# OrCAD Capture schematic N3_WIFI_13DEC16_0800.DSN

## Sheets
1 PAGE2: size C
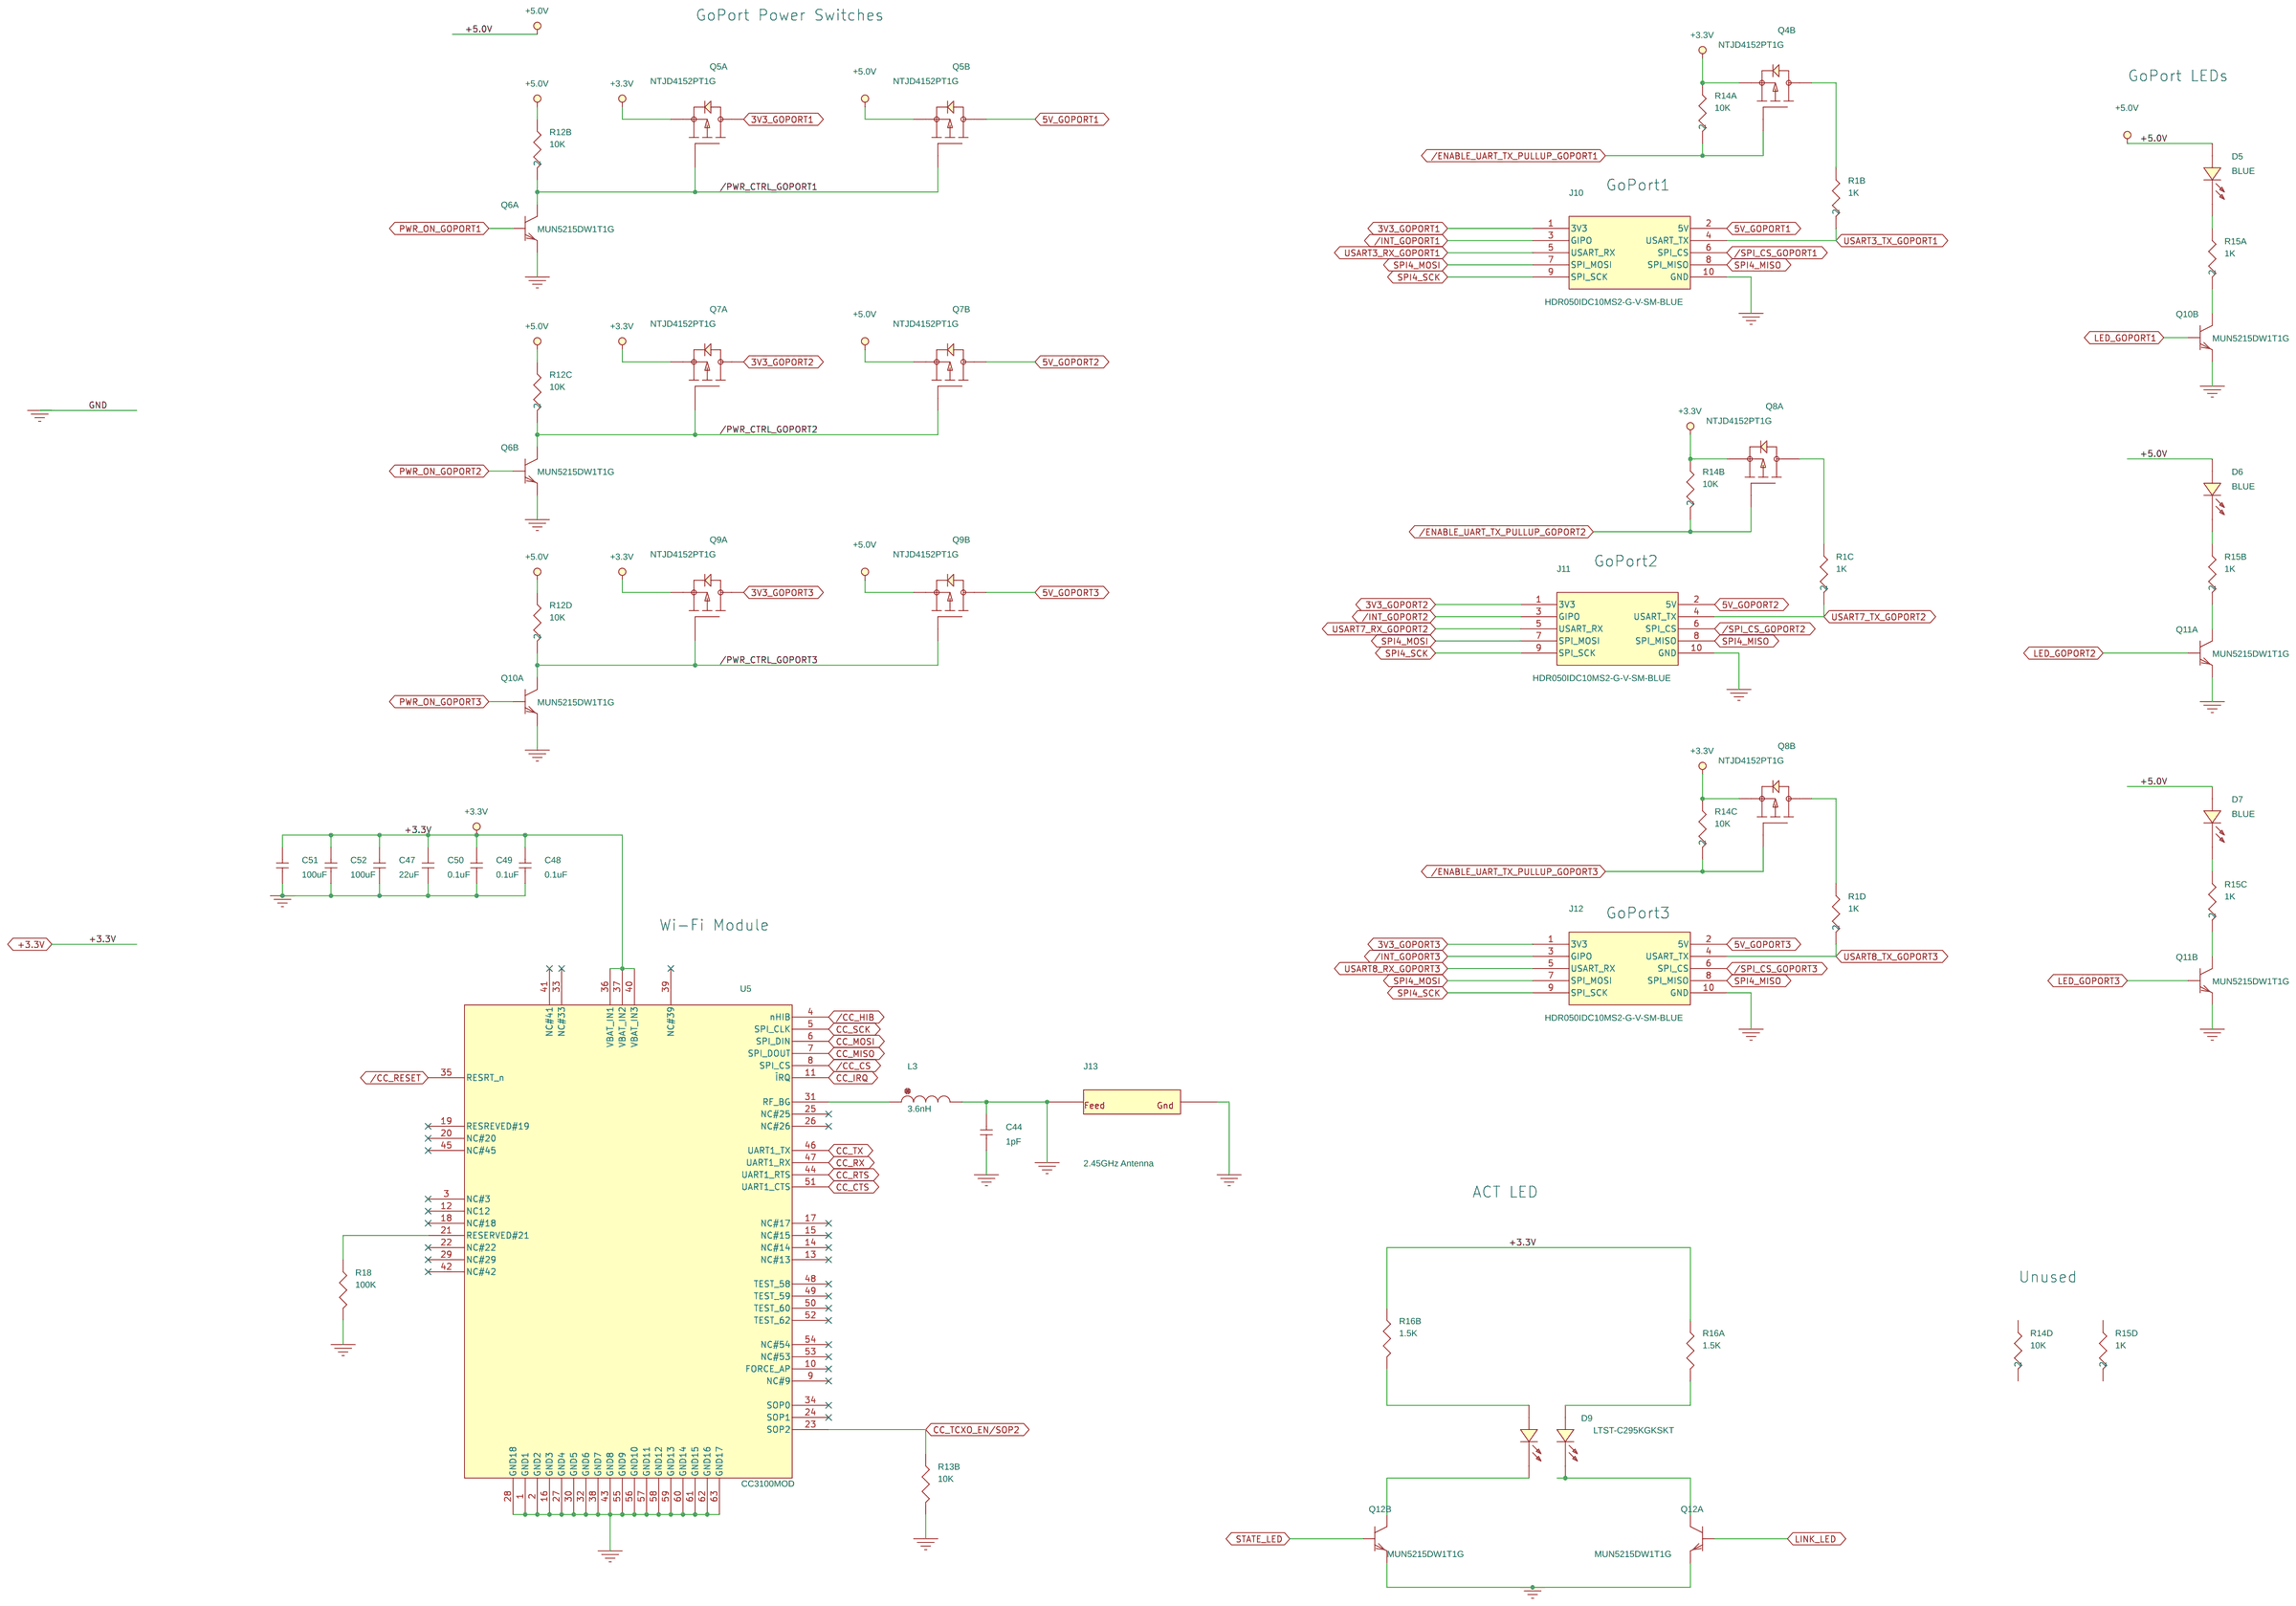
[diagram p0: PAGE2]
2 PAGE1: size C
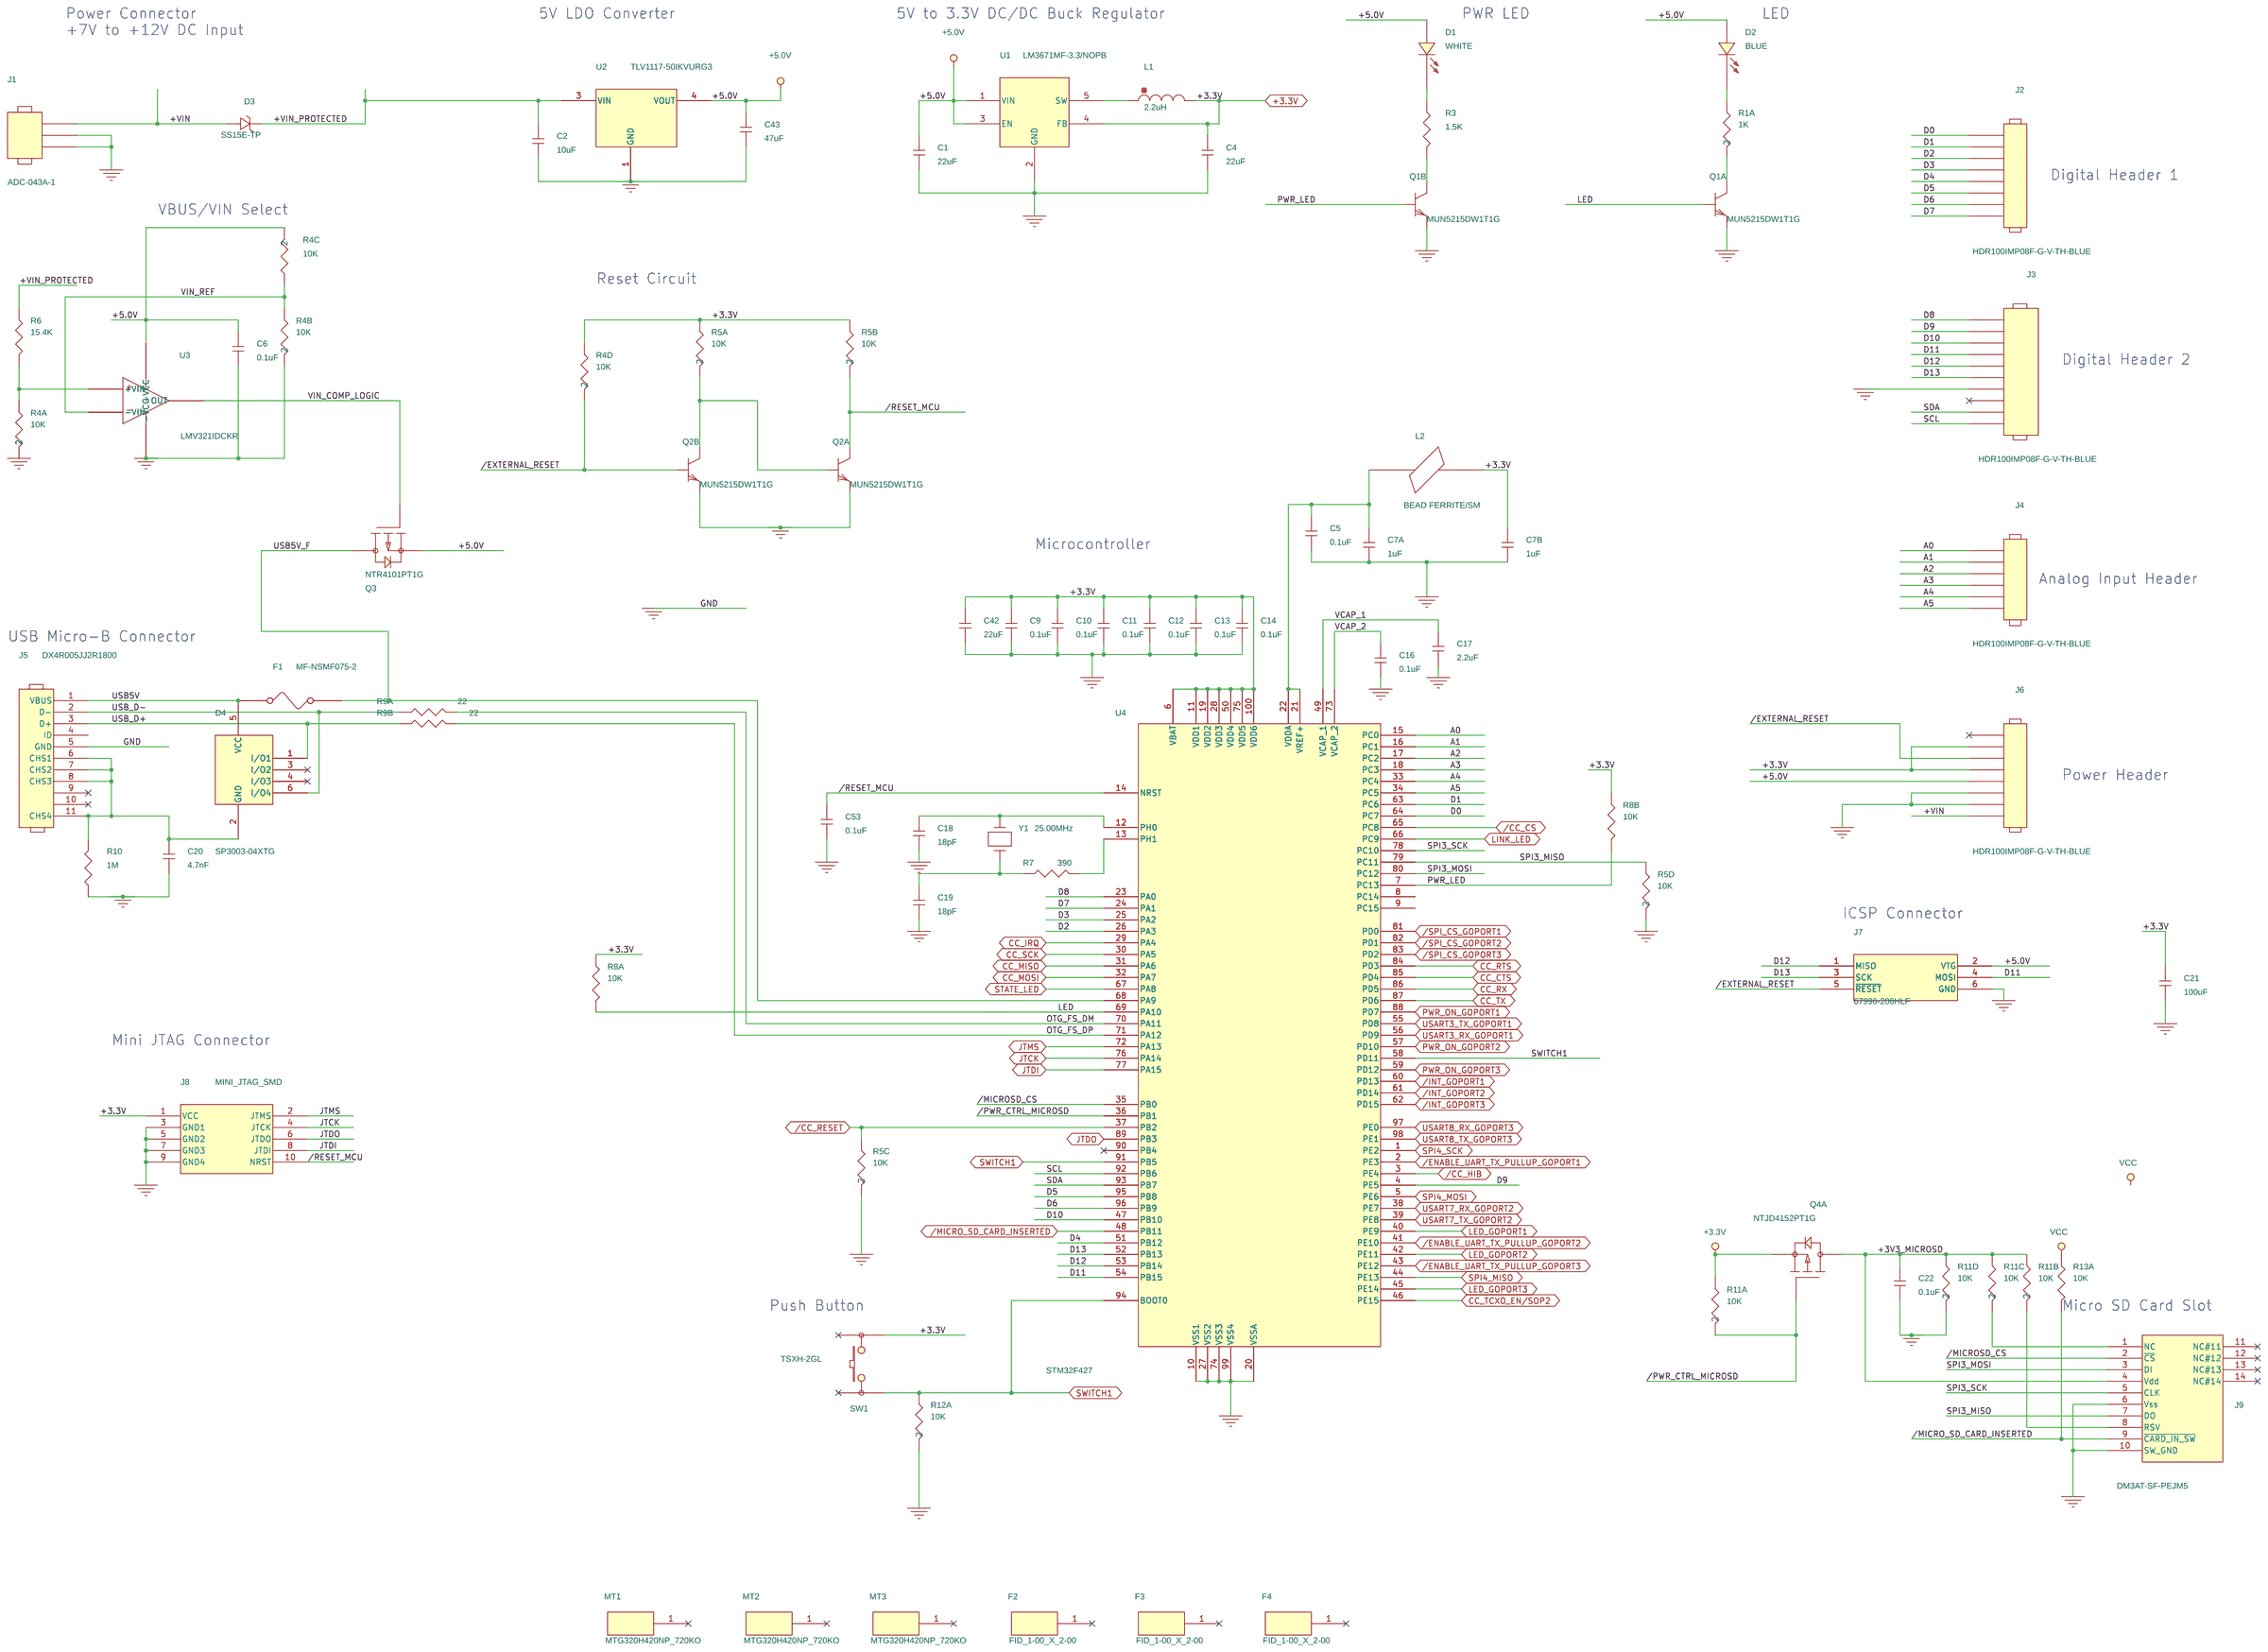
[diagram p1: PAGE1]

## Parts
sheet PAGE1
C1  22uF  [CAPC3216X180N]
C2  10uF  [CAPC2012X125N]
C4  22uF  [CAPC2012X125N]
C5  0.1uF  [CAPC1005X55N]
C6  0.1uF  [CAPC1005X55N]
C7  1uF  [GNM1M2]  (sections A,B)
C9  0.1uF  [CAP-0201]
C10  0.1uF  [CAPC1005X55N]
C11  0.1uF  [CAPC1005X55N]
C12  0.1uF  [CAPC1005X55N]
C13  0.1uF  [CAPC1005X55N]
C14  0.1uF  [CAPC1005X55N]
C16  0.1uF  [CAPC1005X55N]
C17  2.2uF  [CAPC1005X55N]
C18  18pF  [CAPC1005X55N]
C19  18pF  [CAPC1005X55N]
C20  4.7nF  [CAPC1005X55N]
C21  100uF  [CAPMP6032X280N]
C22  0.1uF  [CAPC1005X55N]
C42  22uF  [CAPC2012X125N]
C43  47uF  [F931A476MBA]
C53  0.1uF  [CAP-0201]
D1  WHITE  [LEDC2012X110N]
D2  BLUE  [LEDC2012X110N]
D3  SS15E-TP  [SS15-TP]
D4  SP3003-04XTG  [SP3003-04XTG]
F1  MF-NSMF075-2  [RESC3216X100N]
F2  FID_1-00_X_2-00  [FID_1-00_X_2-00]
F3  FID_1-00_X_2-00  [FID_1-00_X_2-00]
F4  FID_1-00_X_2-00  [FID_1-00_X_2-00]
J1  ADC-043A-1  [ADC-043A-1]
J2  HDR100IMP08F-G-V-TH-BLUE  [HDR100IMP08F-G-V-TH]
J3  HDR100IMP08F-G-V-TH-BLUE  [HDR100IMP10F-G-V-TH]
J4  HDR100IMP08F-G-V-TH-BLUE  [HDR100IMP06F-G-V-TH]
J5  DX4R005JJ2R1800  [DX4R005JJ2R1800]
J6  HDR100IMP08F-G-V-TH-BLUE  [HDR100IMP08F-G-V-TH]
J7  67996-206HLF  [67996-206HLF]
J8  MINI_JTAG_SMD  [MINI_JTAG_SMD]
J9  DM3AT-SF-PEJM5  [DM3AT-SF-PEJ]
L1  2.2uH  [LQH3NPN2R2NM0L]
L2  BEAD FERRITE/SM  [INDC1005X55N]
MT1  MTG320H420NP_720KO  [MTG320H420NP_720KO]
MT2  MTG320H420NP_720KO  [MTG320H420NP_720KO]
MT3  MTG320H420NP_720KO  [MTG320H420NP_720KO]
Q1  MUN5215DW1T1G  [MUN5215DW1T1G]  (sections A,B)
Q2  MUN5215DW1T1G  [MUN5215DW1T1G]  (sections A,B)
Q3  NTR4101PT1G  [NTR4101PT1G]
R3  1.5K  [RESC1005X40AN]
R4  10K  [RESCAV50P80X160X60-8N]  (sections A,B,C,D)
R5  10K  [RESCAV50P80X160X60-8N]  (sections A,B,C,D)
R6  15.4K  [RESC1005X40AN]
R7  390  [RESC1005X40AN]
R8  10K  [EXB24V]  (sections A,B)
R9  22  [EXB24V]  (sections A,B)
R10  1M  [RESC1005X40AN]
R11  10K  [RESCAV50P80X160X60-8N]  (sections A,B,C,D)
SW1  TSXH-2GL  [TSXH-2GL]
U1  LM3671MF-3.3/NOPB  [LM3671MF]
U2  TLV1117-50IKVURG3  [TLV1117-50IKVURG3]
U3  LMV321IDCKR  [LMV321IDCKR]
U4  STM32F427  [STM32F427VIT6]
Y1  25.00MHz  [ABM7]
sheet PAGE2
C44  1pF  [CAPC1005X55N]
C47  22uF  [CAPC2012X125N]
C48  0.1uF  [CAPC1005X55N]
C49  0.1uF  [CAPC1005X55N]
C50  0.1uF  [CAPC1005X55N]
C51  100uF  [CAPMP6032X280N]
C52  100uF  [CAPMP6032X280N]
D5  BLUE  [LEDC1608X80N]
D6  BLUE  [LEDC1608X80N]
D7  BLUE  [LEDC1608X80N]
D9  LTST-C295KGKSKT  [LTST-C295]
J10  HDR050IDC10MS2-G-V-SM-BLUE  [20021521-00010T1LF]
J11  HDR050IDC10MS2-G-V-SM-BLUE  [20021521-00010T1LF]
J12  HDR050IDC10MS2-G-V-SM-BLUE  [20021521-00010T1LF]
J13  2.45GHz Antenna  [AH316M245001-T]
L3  3.6nH  [RESC1005X40AN]
Q4  NTJD4152PT1G  [NTJD4152PT1G]  (sections A,B)
Q5  NTJD4152PT1G  [NTJD4152PT1G]  (sections A,B)
Q6  MUN5215DW1T1G  [MUN5215DW1T1G]  (sections A,B)
Q7  NTJD4152PT1G  [NTJD4152PT1G]  (sections A,B)
Q8  NTJD4152PT1G  [NTJD4152PT1G]  (sections A,B)
Q9  NTJD4152PT1G  [NTJD4152PT1G]  (sections A,B)
Q10  MUN5215DW1T1G  [MUN5215DW1T1G]  (sections A,B)
Q11  MUN5215DW1T1G  [MUN5215DW1T1G]  (sections A,B)
Q12  MUN5215DW1T1G  [MUN5215DW1T1G]  (sections A,B)
R1  1K  [RESCAV50P80X160X60-8N]  (sections A,B,C,D)
R12  10K  [RESCAV50P80X160X60-8N]  (sections A,B,C,D)
R13  10K  [EXB24V]  (sections A,B)
R14  10K  [RESCAV50P80X160X60-8N]  (sections A,B,C,D)
R15  1K  [RESCAV50P80X160X60-8N]  (sections A,B,C,D)
R16  1.5K  [EXB24V]  (sections A,B)
R18  100K  [RESC1005X40AN]
U5  CC3100MOD  [CC3100MOD]

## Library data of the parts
C1 C2 C4-C6 C9-C14 C16-C22 C42-C44 C47-C53 = C
C7 = GNM1M2
D1 = LED_2
D2 D5-D7 = LED_1
D3 = D05AZ75_0
D4 = HEADER_6_0
F1 = FUSE
F2-F4 MT1-MT3 = MOUNT_HOLE
J1 = HEADER_3
J2 J6 = HEADER_8
J3 = HEADER_10
J4 = HEADER_6
J5 = HEADER_11_0
J7 = HEADER_6_1
J8 = HEADER_10_2_v2
J9 = HEADER_10_4
L1 L3 = L
L2 = BEAD_FERRITE_SM
Q1 Q2 Q12 = MUN5215DW1T1G_3
Q3 = NDF0610_TO_1
R3 R6 R7 R10 R18 = R
R1 R4 R5 R11 R12 R14 R15 = RESCAV50P80X160X60-8N
R8 R9 R13 R16 = EXB24V
SW1 = SW_PUSHBUTTON-SPST-2_0
U1 = HEADER_5_0
U2 = LM7805_TO_2
U3 = LMV321_SO
U4 = STM32F427_0
Y1 = CRYSTAL
D9 = LED_0
J10-J12 = HEADER_10_2
J13 = HEADER_2_0
Q4 Q5 Q7-Q9 = NTJD4152PT1G
Q6 Q10 Q11 = MUN5215DW1T1G_0
U5 = CC3100MOD_WIFI_MODULE_1

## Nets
3V3_GOPORT1: J10.1(3V3) Q5.6(DRAIN)
3V3_GOPORT2: J11.1(3V3) Q7.6(DRAIN)
3V3_GOPORT3: J12.1(3V3) Q9.6(DRAIN)
5V_GOPORT1: J10.2(5V) Q5.3(DRAIN)
5V_GOPORT2: J11.2(5V) Q7.3(DRAIN)
5V_GOPORT3: J12.2(5V) Q9.3(DRAIN)
+3.3V: C4.1 C7.2 C9.1 C10.1 C11.1 C12.1 C13.1 C14.1 C21.1 C42.1 C47.1 C48.1 C49.1 C50.1 C51.1 C52.1 J6.2 J6.4 J8.1(VCC) L1.2 L2.2 Q4.1(SOURCE) Q4.4(SOURCE) Q5.1(SOURCE) Q7.1(SOURCE) Q8.1(SOURCE) Q8.4(SOURCE) Q9.1(SOURCE) R4.4 R5.1 R5.2 R8.1 R8.2 R11.1 R13.1 R14.1 R14.2 R14.3 R16.1 R16.2 SW1.2 U1.4(FB) U4.6(VBAT) U4.11(VDD1) U4.19(VDD2) U4.28(VDD3) U4.50(VDD4) U4.75(VDD5) U4.100(VDD6) U5.36(VBAT_IN1) U5.37(VBAT_IN2) U5.40(VBAT_IN3)
+3V3_MICROSD: C22.1 J9.4(Vdd) Q4.6(DRAIN) R11.2 R11.3 R11.4
+5.0V: C1.1 C6.1 C43.1 D1.A(ANODE) D2.A(ANODE) D5.A(ANODE) D6.A(ANODE) D7.A(ANODE) J6.5 J7.2(VTG) Q3.2(SOURCE) Q5.4(SOURCE) Q7.4(SOURCE) Q9.4(SOURCE) R4.6(2) R12.2 R12.3 R12.4 U1.1(VIN) U1.3(EN) U2.4(VOUT) U3.5(+VCC)
+VIN: D3.A(1) J1.1 J6.8
+VIN_PROTECTED: C2.1 D3.C(2) R6.1 U2.3(VIN)
GND: C1.2 C2.2 C4.2 C5.2 C6.2 C7.3 C7.4(3) C9.2 C10.2 C11.2 C12.2 C13.2 C14.2 C16.2 C17.2 C18.2 C19.2 C20.1 C21.2 C22.2 C42.2 C43.2 C44.1 C44.2 C47.2 C48.2 C49.2 C50.2 C51.2 C52.2 C53.2 J1.2 J1.3 J3.7 J5.5(GND) J6.6 J6.7 J7.6(GND) J8.3(GND1) J8.5(GND2) J8.7(GND3) J8.9(GND4) J9.6(Vss) J9.10(SW_GND) J10.10(GND) J11.10(GND) J12.10(GND) J13.1 J13.2 L3.2 Q1.1(e) Q1.4(e) Q2.1(e) Q2.4(e) Q6.1(e) Q6.4(e) Q10.1(e) Q10.4(e) Q11.1(e) Q11.4(e) Q12.1(e) Q12.4(e) R4.7(2) R4.8(2) R5.5(2) R5.6(2) R10.1 R11.5(2) R12.8(2) R13.3(2) R18.2 U1.2(GND) U2.1(GND) U3.2(-VCC) U4.10(VSS1) U4.20(VSSA) U4.27(VSS2) U4.74(VSS3) U4.99(VSS4) U5.1(GND1) U5.2(GND2) U5.16(GND3) U5.27(GND4) U5.28(GND18) U5.30(GND5) U5.32(GND6) U5.38(GND7) U5.43(GND8) U5.55(GND9) U5.56(GND10) U5.57(GND11) U5.58(GND12) U5.59(GND13) U5.60(GND14) U5.61(GND15) U5.62(GND16) U5.63(GND17)
VIN_COMP_LOGIC: Q3.1(GATE) U3.4(OUT)
VIN_REF: R4.2 R4.3 U3.3(-VIN)
/CC_CS: U4.65(PC8) U5.8(SPI_CS)
/CC_HIB: U4.3(PE4) U5.4(nHIB)
/CC_RESET: R5.3 U4.37(PB2) U5.35(RESRT_n)
/ENABLE_UART_TX_PULLUP_GOPORT1: Q4.5(GATE) R14.8(2) U4.2(PE3)
/ENABLE_UART_TX_PULLUP_GOPORT2: Q8.2(GATE) R14.7(2) U4.41(PE10)
/ENABLE_UART_TX_PULLUP_GOPORT3: Q8.5(GATE) R14.6(2) U4.43(PE12)
/EXTERNAL_RESET: J6.3 J7.5(~{RESET}) Q2.5(b) R4.5(2)
/INT_GOPORT1: J10.3(GIPO) U4.60(PD13)
/INT_GOPORT2: J11.3(GIPO) U4.61(PD14)
/INT_GOPORT3: J12.3(GIPO) U4.62(PD15)
/MICRO_SD_CARD_INSERTED: J9.9(~{CARD_IN_SW}) R13.4(2) U4.48(PB11)
/MICROSD_CS: J9.2(~{CS}) U4.35(PB0)
/PWR_CTRL_GOPORT1: Q5.2(GATE) Q5.5(GATE) Q6.3(c) R12.7(2)
/PWR_CTRL_GOPORT2: Q6.6(c) Q7.2(GATE) Q7.5(GATE) R12.6(2)
/PWR_CTRL_GOPORT3: Q9.2(GATE) Q9.5(GATE) Q10.3(c) R12.5(2)
/PWR_CTRL_MICROSD: Q4.2(GATE) R11.8(2) U4.36(PB1)
/RESET_MCU: C53.1 J8.10(NRST) Q2.6(c) R5.7(2) U4.14(NRST)
/SPI_CS_GOPORT1: J10.6(SPI_CS) U4.81(PD0)
/SPI_CS_GOPORT2: J11.6(SPI_CS) U4.82(PD1)
/SPI_CS_GOPORT3: J12.6(SPI_CS) U4.83(PD2)
A0: J4.1 U4.15(PC0)
A1: J4.2 U4.16(PC1)
A2: J4.3 U4.17(PC2)
A3: J4.4 U4.18(PC3)
A4: J4.5 U4.33(PC4)
A5: J4.6 U4.34(PC5)
CC_CTS: U4.85(PD4) U5.51(UART1_CTS)
CC_IRQ: U4.29(PA4) U5.11(~{I}RQ)
CC_MISO: U4.31(PA6) U5.7(SPI_DOUT)
CC_MOSI: U4.32(PA7) U5.6(SPI_DIN)
CC_RTS: U4.84(PD3) U5.44(UART1_RTS)
CC_RX: U4.86(PD5) U5.47(UART1_RX)
CC_SCK: U4.30(PA5) U5.5(SPI_CLK)
CC_TCXO_EN/SOP2: R13.2 U4.46(PE15) U5.23(SOP2)
CC_TX: U4.87(PD6) U5.46(UART1_TX)
D0: J2.1 U4.64(PC7)
D1: J2.2 U4.63(PC6)
D2: J2.3 U4.26(PA3)
D3: J2.4 U4.25(PA2)
D4: J2.5 U4.51(PB12)
D5: J2.6 U4.95(PB8)
D6: J2.7 U4.96(PB9)
D7: J2.8 U4.24(PA1)
D8: J3.1 U4.23(PA0)
D9: J3.2 U4.4(PE5)
D10: J3.3 U4.47(PB10)
D11: J3.4 J7.4(MOSI) U4.54(PB15)
D12: J3.5 J7.1(MISO) U4.53(PB14)
D13: J3.6 J7.3(SCK) U4.52(PB13)
JTCK: J8.4(JTCK) U4.76(PA14)
JTDI: J8.8(JTDI) U4.77(PA15)
JTDO: J8.6(JTDO) U4.89(PB3)
JTMS: J8.2(JTMS) U4.72(PA13)
LED: Q1.2(b) R8.4(2) U4.69(PA10)
LED_GOPORT1: Q10.2(b) U4.40(PE9)
LED_GOPORT2: Q11.5(b) U4.42(PE11)
LED_GOPORT3: Q11.2(b) U4.45(PE14)
LINK_LED: Q12.2(b) U4.66(PC9)
OTG_FS_DM: R9.4(2) U4.70(PA11)
OTG_FS_DP: R9.3(2) U4.71(PA12)
PWR_LED: Q1.5(b) R8.3(2) U4.7(PC13)
PWR_ON_GOPORT1: Q6.5(b) U4.88(PD7)
PWR_ON_GOPORT2: Q6.2(b) U4.57(PD10)
PWR_ON_GOPORT3: Q10.5(b) U4.59(PD12)
SCL: J3.10 U4.92(PB6)
SDA: J3.9 U4.93(PB7)
SPI3_MISO: J9.7(DO) R5.4 U4.79(PC11)
SPI3_MOSI: J9.3(DI) U4.80(PC12)
SPI3_SCK: J9.5(CLK) U4.78(PC10)
SPI4_MISO: J10.8(SPI_MISO) J11.8(SPI_MISO) J12.8(SPI_MISO) U4.44(PE13)
SPI4_MOSI: J10.7(SPI_MOSI) J11.7(SPI_MOSI) J12.7(SPI_MOSI) U4.5(PE6)
SPI4_SCK: J10.9(SPI_SCK) J11.9(SPI_SCK) J12.9(SPI_SCK) U4.1(PE2)
STATE_LED: Q12.5(b) U4.67(PA8)
SWITCH1: R12.1 SW1.4 U4.58(PD11) U4.91(PB5) U4.94(BOOT0)
USART3_RX_GOPORT1: J10.5(USART_RX) U4.56(PD9)
USART3_TX_GOPORT1: J10.4(USART_TX) R1.7(2) U4.55(PD8)
USART7_RX_GOPORT2: J11.5(USART_RX) U4.38(PE7)
USART7_TX_GOPORT2: J11.4(USART_TX) R1.6(2) U4.39(PE8)
USART8_RX_GOPORT3: J12.5(USART_RX) U4.97(PE0)
USART8_TX_GOPORT3: J12.4(USART_TX) R1.5(2) U4.98(PE1)
USB5V: D4.5(VCC) F1.1 J5.1(VBUS)
USB5V_F: F1.2 Q3.3(DRAIN) U4.68(PA9)
USB_D+: D4.1(I/O1) J5.3(D+) R9.2
USB_D-: D4.6(I/O4) J5.2(D-) R9.1
VCAP_1: C17.1 U4.49(VCAP_1)
VCAP_2: C16.1 U4.73(VCAP_2)
N61621: C20.2 D4.2(GND) J5.6(CHS1) J5.7(CHS2) J5.8(CHS3) J5.11(CHS4) R10.2
N62667: R4.1 R6.2 U3.1(+VIN)
N62753: Q2.2(b) Q2.3(c) R5.8(2)
N62779: L1.1 U1.5(SW)
N62801: D2.C(CATHODE) R1.1
N62883: J9.1(NC) R11.6(2)
N62887: J9.8(RSV) R11.7(2)
N63081: C5.1 C7.1 L2.1 U4.21(VREF+) U4.22(VDDA)
N63113: C18.1 U4.12(PH0) Y1.2
N63117: R7.2 U4.13(PH1)
N63121: C19.1 R7.1 Y1.1
N74908: Q1.6(c) R1.8(2)
N77511: D1.C(CATHODE) R3.1
N77515: Q1.3(c) R3.2
N83970: D9.4(CATHODE) Q12.3(c)
N84209: D9.3(CATHODE_1) Q12.6(c)
N89038: L3.1 U5.31(RF_BG)
N89104: D9.2(ANODE) R16.3(2)
N89108: D9.1(ANODE) R16.4(2)
N89134: R18.1 U5.21(RESERVED#21)
N197515: Q10.6(c) R15.8(2)
N197535: D5.C(CATHODE) R15.1
N197921: Q11.3(c) R15.7(2)
N197949: D6.C(CATHODE) R15.2
N198166: Q11.6(c) R15.6(2)
N198194: D7.C(CATHODE) R15.3
N199051: Q4.3(DRAIN) R1.2
N202411: Q8.6(DRAIN) R1.3
N203046: Q8.3(DRAIN) R1.4

Not connected (* = marked no-connect by the designer): D4 3(I/O2)* 4(I/O3)*; F2 1*; F3 1*; F4 1*; J3 8*; J5 4(ID) 9* 10*; J6 1*; J9 11(NC#11)* 12(NC#12)* 13(NC#13)* 14(NC#14)*; MT1 1*; MT2 1*; MT3 1*; R14 4 5(2); R15 4 5(2); SW1 1* 3*; U4 8(PC14) 9(PC15) 90(PB4)*; U5 3(NC#3)* 9(NC#9)* 10(FORCE_AP)* 12(NC12)* 13(NC#13)* 14(NC#14)* 15(NC#15)* 17(NC#17)* 18(NC#18)* 19(RESREVED#19)* 20(NC#20)* 22(NC#22)* 24(SOP1)* 25(NC#25)* 26(NC#26)* 29(NC#29)* 33(NC#33)* 34(SOP0)* 39(NC#39)* 41(NC#41)* 42(NC#42)* 45(NC#45)* 48(TEST_58)* 49(TEST_59)* 50(TEST_60)* 52(TEST_62)* 53(NC#53)* 54(NC#54)*

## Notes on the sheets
sheet 1
- GoPort Power Switches
- GoPort LEDs
- GoPort1
- GoPort2
- GoPort3
- Wi-Fi Module
- ACT LED
- Unused
sheet 2
- Power Connector
  +7V to +12V DC Input
- 5V LDO Converter
- 5V to 3.3V DC/DC Buck Regulator
- PWR LED
- LED
- Digital Header 1
- VBUS/VIN Select
- Reset Circuit
- Digital Header 2
- Microcontroller
- Analog Input Header
- USB Micro-B Connector
- Power Header
- ICSP Connector
- Mini JTAG Connector
- Push Button
- Micro SD Card Slot
